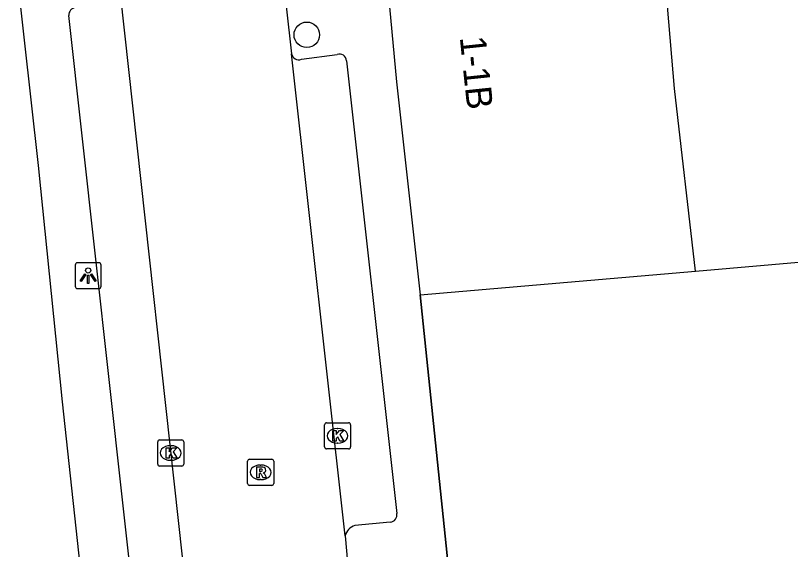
# Model space of a CAD drawing. Extents: x 159961 to 160856, y 382704 to 383353.
# Drawn here: x 160062.51 to 160092.25, y 383257.01 to 383277.5 of the extents above; entities that cross this region are included whole.
import ezdxf

# ---------------------------------------------------------------- set-up
doc = ezdxf.new("R2010")
doc.units = 0
for name, color, linetype in [('IMGEO_Boom', 7, 'Continuous'), ('IMGEO_Kolk', 7, 'Continuous'), ('IMGEO_Lichtpunt', 7, 'Continuous'), ('IMGEO_Muur', 7, 'Continuous'), ('IMGEO_Pand', 7, 'Continuous'), ('IMGEO_Pand_nummerreeks', 7, 'Continuous'), ('IMGEO_Rijbaan_lokaal_open', 7, 'Continuous'), ('IMGEO_Rioolput', 7, 'Continuous'), ('IMGEO_Voetpad_open', 7, 'Continuous')]:
    doc.layers.add(name, color=color, linetype=linetype)

msp = doc.modelspace()

# ---------------------------------------------------------------- linework, layer by layer
at = {"layer": 'IMGEO_Boom'}
msp.add_circle((160073.689, 383276.76), 0.489, dxfattribs=at)
at = {"layer": 'IMGEO_Kolk'}
for p, q in [((160074.443, 383261.869), (160075.295, 383261.869)), ((160074.368, 383260.943), (160074.368, 383261.795)), ((160074.856, 383261.649), (160074.881, 383261.649)), ((160075.369, 383261.795), (160075.369, 383260.943)), ((160067.967, 383260.285), (160067.967, 383261.137)), ((160068.042, 383261.211), (160068.894, 383261.211)), ((160068.455, 383260.991), (160068.48, 383260.991)), ((160068.968, 383261.137), (160068.968, 383260.285)), ((160074.879, 383261.089), (160074.854, 383261.089)), ((160075.295, 383260.869), (160074.443, 383260.869)), ((160068.478, 383260.431), (160068.453, 383260.431)), ((160068.894, 383260.211), (160068.042, 383260.211))]:
    msp.add_line(p, q, dxfattribs=at)
for points in [[(160074.443, 383261.869), (160075.295, 383261.869)], [(160074.368, 383260.943), (160074.368, 383261.795)], [(160074.689, 383261.569), (160074.812, 383261.569), (160074.812, 383261.418), (160074.942, 383261.569), (160075.106, 383261.569), (160074.96, 383261.418), (160075.113, 383261.169), (160074.961, 383261.169), (160074.876, 383261.333), (160074.812, 383261.266), (160074.812, 383261.169), (160074.689, 383261.169), (160074.689, 383261.569)], [(160075.369, 383261.795), (160075.369, 383260.943)], [(160067.967, 383260.285), (160067.967, 383261.137)], [(160068.042, 383261.211), (160068.894, 383261.211)], [(160068.968, 383261.137), (160068.968, 383260.285)], [(160068.288, 383260.911), (160068.411, 383260.911), (160068.411, 383260.76), (160068.541, 383260.911), (160068.705, 383260.911), (160068.559, 383260.76), (160068.712, 383260.511), (160068.56, 383260.511), (160068.475, 383260.675), (160068.411, 383260.608), (160068.411, 383260.511), (160068.288, 383260.511), (160068.288, 383260.911)], [(160075.295, 383260.869), (160074.443, 383260.869)], [(160068.894, 383260.211), (160068.042, 383260.211)]]:
    msp.add_lwpolyline(points, dxfattribs=at)
for centre, start, end in [((160074.445, 383261.793), 91.552, 178.448), ((160074.445, 383261.793), 91.552, 178.448), ((160075.293, 383261.793), 1.552, 88.448), ((160075.293, 383261.793), 1.552, 88.448), ((160068.044, 383261.135), 91.552, 178.448), ((160068.044, 383261.135), 91.552, 178.448), ((160068.892, 383261.135), 1.552, 88.448), ((160068.892, 383261.135), 1.552, 88.448), ((160074.445, 383260.945), 181.552, 268.448), ((160074.445, 383260.945), 181.552, 268.448), ((160075.293, 383260.945), 271.552, 358.448), ((160075.293, 383260.945), 271.552, 358.448), ((160068.044, 383260.287), 181.552, 268.448), ((160068.044, 383260.287), 181.552, 268.448), ((160068.892, 383260.287), 271.552, 358.448), ((160068.892, 383260.287), 271.552, 358.448)]:
    msp.add_arc(centre, 0.0765, start, end, dxfattribs=at)
for centre, major_axis, ratio, start_param, end_param in [((160074.855, 383261.369), (-0.387, 0.002), 0.722429, 4.712389, 7.853982), ((160074.88, 383261.369), (-0.39, 0.002), 0.717154, 1.570796, 4.712389), ((160068.454, 383260.711), (-0.387, 0.002), 0.722429, 4.712389, 7.853982), ((160068.479, 383260.711), (-0.39, 0.002), 0.717154, 1.570796, 4.712389)]:
    msp.add_ellipse(centre, major_axis=major_axis, ratio=ratio, start_param=start_param, end_param=end_param, dxfattribs=at)
at = {"layer": 'IMGEO_Lichtpunt'}
for p, q in [((160064.801, 383267.92), (160064.801, 383267.113)), ((160064.801, 383267.92), (160064.801, 383267.113)), ((160065.703, 383268.015), (160064.895, 383268.015)), ((160065.703, 383268.015), (160064.895, 383268.015)), ((160065.797, 383267.113), (160065.797, 383267.92)), ((160065.797, 383267.113), (160065.797, 383267.92)), ((160064.895, 383267.019), (160065.703, 383267.019)), ((160064.895, 383267.019), (160065.703, 383267.019))]:
    msp.add_line(p, q, dxfattribs=at)
for points in [[(160065.175, 383267.584), (160065.214, 383267.556), (160065.026, 383267.294), (160064.988, 383267.321), (160065.175, 383267.584)], [(160065.277, 383267.536), (160065.324, 383267.536), (160065.324, 383267.214), (160065.277, 383267.214), (160065.277, 383267.536)], [(160065.387, 383267.556), (160065.425, 383267.583), (160065.612, 383267.321), (160065.573, 383267.293), (160065.387, 383267.556)]]:
    msp.add_lwpolyline(points, dxfattribs=at)
msp.add_circle((160065.3, 383267.718), 0.0994, dxfattribs=at)
for centre, start, end in [((160064.895, 383267.92), 90, 180), ((160064.895, 383267.92), 90, 180), ((160065.703, 383267.92), 0, 90), ((160065.703, 383267.92), 0, 90), ((160064.895, 383267.113), 180, 270), ((160064.895, 383267.113), 180, 270), ((160065.703, 383267.113), 270, 0), ((160065.703, 383267.113), 270, 360)]:
    msp.add_arc(centre, 0.0946, start, end, dxfattribs=at)
at = {"layer": 'IMGEO_Muur'}
msp.add_lwpolyline([(160078.039, 383266.783), (160079.706, 383250.732)], dxfattribs=at)
at = {"layer": 'IMGEO_Pand'}
for points in [[(160088.605, 383267.694), (160087.795, 383274.695), (160087.099, 383282.985)], [(160076.472, 383282.097), (160077.135, 383274.96), (160078.039, 383266.783)], [(160062.543, 383279.597), (160062.511, 383279.566), (160062.564, 383279.089), (160063.376, 383271.746), (160064.297, 383262.679), (160065.133, 383254.986)], [(160088.605, 383267.694), (160092.853, 383268.061), (160096.951, 383260.655), (160099.564, 383262.101)], [(160078.039, 383266.783), (160088.605, 383267.694)]]:
    msp.add_lwpolyline(points, dxfattribs=at)
at = {"layer": 'IMGEO_Rijbaan_lokaal_open'}
for points in [[(160072.54, 383281.057), (160072.684, 383279.818), (160073.105, 383276.032)], [(160066.525, 383278.346), (160069.226, 383253.828)], [(160075.159, 383257.527), (160073.105, 383276.032)], [(160075.159, 383257.527), (160075.453, 383254.2), (160075.85, 383250.385)]]:
    msp.add_lwpolyline(points, dxfattribs=at)
at = {"layer": 'IMGEO_Rioolput'}
for p, q in [((160071.417, 383259.542), (160071.417, 383260.394)), ((160071.492, 383260.468), (160072.344, 383260.468)), ((160072.418, 383260.394), (160072.418, 383259.542)), ((160071.905, 383260.248), (160071.93, 383260.248)), ((160071.928, 383259.688), (160071.903, 383259.688)), ((160072.344, 383259.468), (160071.492, 383259.468))]:
    msp.add_line(p, q, dxfattribs=at)
for points in [[(160071.417, 383259.542), (160071.417, 383260.394)], [(160071.492, 383260.468), (160072.344, 383260.468)], [(160072.418, 383260.394), (160072.418, 383259.542)], [(160072.006, 383260.166), (160071.754, 383260.168), (160071.754, 383259.768)], [(160071.932, 383260.087), (160071.878, 383260.087), (160071.878, 383260.006)], [(160071.754, 383259.768), (160071.878, 383259.768), (160071.878, 383259.93), (160071.889, 383259.93)], [(160071.878, 383260.006), (160071.93, 383260.006)], [(160071.936, 383259.901), (160072.007, 383259.768), (160072.147, 383259.768), (160072.082, 383259.894)], [(160072.344, 383259.468), (160071.492, 383259.468)]]:
    msp.add_lwpolyline(points, dxfattribs=at)
for centre, radius, start, end in [((160071.494, 383260.392), 0.0765, 91.552, 178.448), ((160071.494, 383260.392), 0.0765, 91.552, 178.448), ((160072.342, 383260.392), 0.0765, 1.552, 88.448), ((160072.342, 383260.392), 0.0765, 1.552, 88.448), ((160071.938, 383259.991), 0.0964, 77.0061, 93.1865), ((160071.952, 383260.048), 0.0378, 276.6634, 79.6772), ((160072.005, 383260.056), 0.109, 350.3612, 89.416), ((160071.888, 383259.877), 0.0533, 26.0293, 88.6989), ((160071.914, 383260.195), 0.19, 274.7715, 282.9687), ((160072.003, 383260.056), 0.112, 277.5842, 350.9817), ((160071.987, 383259.841), 0.108, 29.5134, 73.7905), ((160071.494, 383259.544), 0.0765, 181.552, 268.448), ((160071.494, 383259.544), 0.0765, 181.552, 268.448), ((160072.342, 383259.544), 0.0765, 271.552, 358.448), ((160072.342, 383259.544), 0.0765, 271.552, 358.448)]:
    msp.add_arc(centre, radius, start, end, dxfattribs=at)
for centre, major_axis, ratio, start_param, end_param in [((160071.904, 383259.968), (-0.387, 0.002), 0.722429, 4.712389, 7.853982), ((160071.929, 383259.968), (-0.39, 0.002), 0.717154, 1.570796, 4.712389)]:
    msp.add_ellipse(centre, major_axis=major_axis, ratio=ratio, start_param=start_param, end_param=end_param, dxfattribs=at)
at = {"layer": 'IMGEO_Voetpad_open'}
for points in [[(160067.123, 383254.29), (160064.56, 383277.501)], [(160073.48, 383275.819), (160074.856, 383276.01)], [(160075.209, 383275.767), (160077.144, 383258.392)], [(160079.706, 383250.732), (160078.039, 383266.783)], [(160076.893, 383258.059), (160075.538, 383257.928)]]:
    msp.add_lwpolyline(points, dxfattribs=at)
for centre, radius, start, end in [((160064.846, 383277.52), 0.286, 96.3771, 183.8636), ((160073.38, 383276.08), 0.279, 189.819, 290.9879), ((160074.938, 383275.752), 0.271, 3.2506, 107.6635), ((160076.87, 383258.337), 0.279, 274.6855, 11.2999), ((160075.676, 383257.418), 0.528, 105.114, 168.1172)]:
    msp.add_arc(centre, radius, start, end, dxfattribs=at)

# ---------------------------------------------------------------- texts
at = {"layer": 'IMGEO_Pand_nummerreeks'}
msp.add_text('1-1B', height=1, rotation=275.9643, dxfattribs=at).set_placement((160079.558, 383276.663))

doc.saveas('drawing.dxf')
